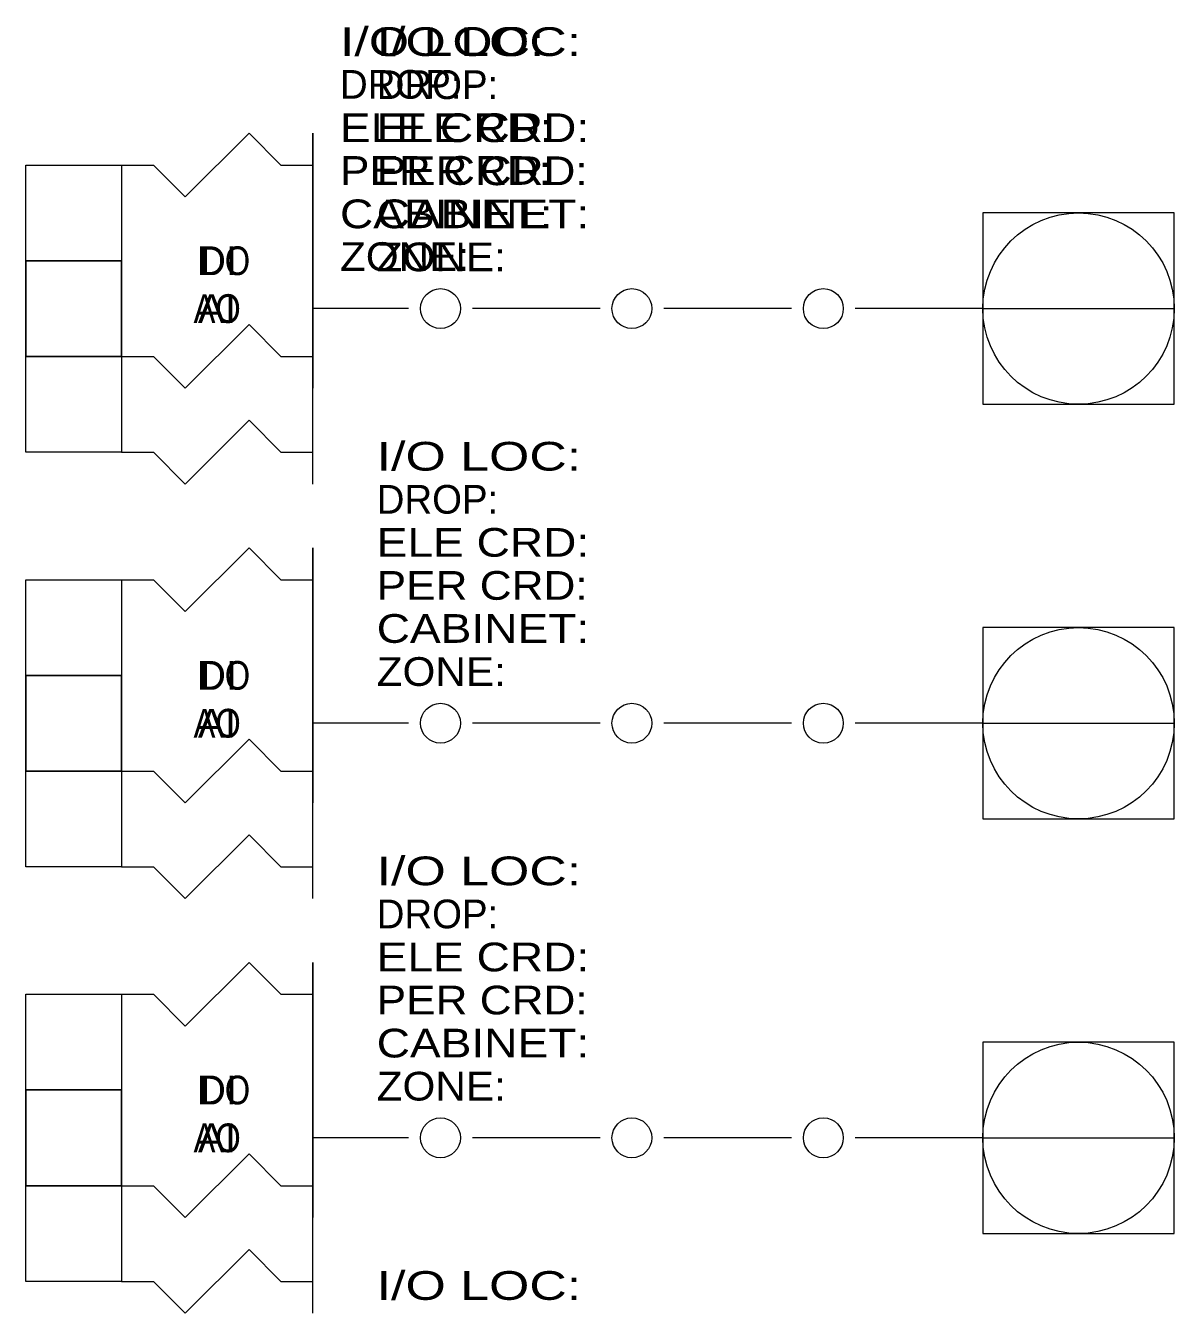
# Model space of a CAD drawing. Extents: x 0.01 to 1.26, y 0 to 0.83.
# Drawn here: x 0.9583 to 1.2583, y 0.4958 to 0.8322 of the extents above; entities that cross this region are included whole.
import ezdxf
from ezdxf.enums import TextEntityAlignment as Align

# ---------------------------------------------------------------- set-up
doc = ezdxf.new("R2010")
doc.units = 0
doc.header["$LTSCALE"] = 0.003
for name, color, linetype, lineweight in [('1', 7, 'Continuous', 13), ('10', 7, 'Continuous', 13), ('11', 7, 'Continuous', 13), ('12', 7, 'Continuous', 13), ('13', 7, 'Continuous', 13), ('14', 7, 'Continuous', 13), ('19', 7, 'Continuous', 13), ('2', 7, 'Continuous', 13), ('20', 7, 'Continuous', 13), ('21', 7, 'Continuous', 13), ('22', 7, 'Continuous', 13), ('23', 7, 'Continuous', 13), ('24', 7, 'Continuous', 13), ('29', 7, 'Continuous', 13), ('3', 7, 'Continuous', 13), ('30', 7, 'Continuous', 13), ('39', 7, 'Continuous', 13), ('4', 7, 'Continuous', 13), ('40', 7, 'Continuous', 13), ('9', 7, 'Continuous', 13)]:
    doc.layers.add(name, color=color, linetype=linetype, lineweight=lineweight)

msp = doc.modelspace()

# ---------------------------------------------------------------- linework, layer by layer
at = {"layer": '1'}
for p, q in [((1.033333, 0.804166), (1.033333, 0.7375)), ((0.958333, 0.770833), (0.958333, 0.745833)), ((0.983333, 0.745833), (0.983333, 0.770833)), ((0.958333, 0.745833), (0.983333, 0.745833))]:
    msp.add_line(p, q, dxfattribs=at)
for points in [[(0.983333, 0.795833), (0.991666, 0.795833), (1, 0.7875), (1.016666, 0.804166), (1.025, 0.795833), (1.033333, 0.795833)], [(0.983333, 0.745833), (0.991666, 0.745833), (1, 0.7375), (1.016666, 0.754166), (1.025, 0.745833), (1.033333, 0.745833)]]:
    msp.add_lwpolyline(points, dxfattribs=at)
msp.add_lwpolyline([(0.958333, 0.795833), (0.983333, 0.795833), (0.983333, 0.770833), (0.958333, 0.770833)], close=True, dxfattribs=at)
at = {"layer": '10'}
for p, q in [((1.058333, 0.758333), (1.033333, 0.758333)), ((1.108333, 0.758333), (1.075, 0.758333)), ((1.158333, 0.758333), (1.125, 0.758333)), ((1.208333, 0.758333), (1.175, 0.758333)), ((1.208333, 0.758333), (1.258333, 0.758333))]:
    msp.add_line(p, q, dxfattribs=at)
msp.add_lwpolyline([(1.208333, 0.783333), (1.208333, 0.733333), (1.258333, 0.733333), (1.258333, 0.783333)], close=True, dxfattribs=at)
for centre, radius in [((1.233333, 0.758333), 0.025), ((1.066666, 0.758333), 0.005208), ((1.116666, 0.758333), 0.005208), ((1.166666, 0.758333), 0.005208)]:
    msp.add_circle(centre, radius, dxfattribs=at)
at = {"layer": '11'}
msp.add_line((1.033333, 0.695833), (1.033333, 0.629166), dxfattribs=at)
for points in [[(0.983333, 0.6875), (0.991666, 0.6875), (1, 0.679166), (1.016666, 0.695833), (1.025, 0.6875), (1.033333, 0.6875)], [(0.958333, 0.6625), (0.958333, 0.6375), (0.983333, 0.6375), (0.983333, 0.6625)], [(0.983333, 0.6375), (0.991666, 0.6375), (1, 0.629166), (1.016666, 0.645833), (1.025, 0.6375), (1.033333, 0.6375)]]:
    msp.add_lwpolyline(points, dxfattribs=at)
msp.add_lwpolyline([(0.958333, 0.6875), (0.983333, 0.6875), (0.983333, 0.6625), (0.958333, 0.6625)], close=True, dxfattribs=at)
at = {"layer": '12'}
for p, q in [((1.033333, 0.695833), (1.033333, 0.629166)), ((0.958333, 0.6625), (0.983333, 0.6625))]:
    msp.add_line(p, q, dxfattribs=at)
for points in [[(0.983333, 0.6875), (0.991666, 0.6875), (1, 0.679166), (1.016666, 0.695833), (1.025, 0.6875), (1.033333, 0.6875)], [(0.983333, 0.6375), (0.991666, 0.6375), (1, 0.629166), (1.016666, 0.645833), (1.025, 0.6375), (1.033333, 0.6375)]]:
    msp.add_lwpolyline(points, dxfattribs=at)
msp.add_lwpolyline([(0.958333, 0.6875), (0.983333, 0.6875), (0.983333, 0.6375), (0.958333, 0.6375)], close=True, dxfattribs=at)
at = {"layer": '13'}
for p, q in [((1.033333, 0.604166), (1.033333, 0.695833)), ((0.958333, 0.6625), (0.983333, 0.6625)), ((0.958333, 0.6375), (0.983333, 0.6375))]:
    msp.add_line(p, q, dxfattribs=at)
for points in [[(0.983333, 0.6875), (0.991666, 0.6875), (1, 0.679166), (1.016666, 0.695833), (1.025, 0.6875), (1.033333, 0.6875)], [(0.983333, 0.6125), (0.991666, 0.6125), (1, 0.604166), (1.016666, 0.620833), (1.025, 0.6125), (1.033333, 0.6125)]]:
    msp.add_lwpolyline(points, dxfattribs=at)
msp.add_lwpolyline([(0.958333, 0.6875), (0.983333, 0.6875), (0.983333, 0.6125), (0.958333, 0.6125)], close=True, dxfattribs=at)
at = {"layer": '14'}
for p, q in [((1.033333, 0.604166), (1.033333, 0.695833)), ((0.958333, 0.6625), (0.983333, 0.6625)), ((0.958333, 0.6375), (0.983333, 0.6375))]:
    msp.add_line(p, q, dxfattribs=at)
for points in [[(0.983333, 0.6875), (0.991666, 0.6875), (1, 0.679166), (1.016666, 0.695833), (1.025, 0.6875), (1.033333, 0.6875)], [(0.983333, 0.6125), (0.991666, 0.6125), (1, 0.604166), (1.016666, 0.620833), (1.025, 0.6125), (1.033333, 0.6125)]]:
    msp.add_lwpolyline(points, dxfattribs=at)
msp.add_lwpolyline([(0.958333, 0.6875), (0.983333, 0.6875), (0.983333, 0.6125), (0.958333, 0.6125)], close=True, dxfattribs=at)
at = {"layer": '19'}
for p, q in [((1.058333, 0.65), (1.033333, 0.65)), ((1.108333, 0.65), (1.075, 0.65)), ((1.158333, 0.65), (1.125, 0.65)), ((1.208333, 0.65), (1.175, 0.65)), ((1.208333, 0.65), (1.258333, 0.65))]:
    msp.add_line(p, q, dxfattribs=at)
msp.add_lwpolyline([(1.208333, 0.675), (1.208333, 0.625), (1.258333, 0.625), (1.258333, 0.675)], close=True, dxfattribs=at)
for centre, radius in [((1.233333, 0.65), 0.025), ((1.066666, 0.65), 0.005208), ((1.116666, 0.65), 0.005208), ((1.166666, 0.65), 0.005208)]:
    msp.add_circle(centre, radius, dxfattribs=at)
at = {"layer": '2'}
for p, q in [((1.033333, 0.804166), (1.033333, 0.7375)), ((0.958333, 0.770833), (0.983333, 0.770833))]:
    msp.add_line(p, q, dxfattribs=at)
for points in [[(0.983333, 0.795833), (0.991666, 0.795833), (1, 0.7875), (1.016666, 0.804166), (1.025, 0.795833), (1.033333, 0.795833)], [(0.983333, 0.745833), (0.991666, 0.745833), (1, 0.7375), (1.016666, 0.754166), (1.025, 0.745833), (1.033333, 0.745833)]]:
    msp.add_lwpolyline(points, dxfattribs=at)
msp.add_lwpolyline([(0.958333, 0.795833), (0.983333, 0.795833), (0.983333, 0.745833), (0.958333, 0.745833)], close=True, dxfattribs=at)
at = {"layer": '20'}
for p, q in [((1.058333, 0.65), (1.033333, 0.65)), ((1.108333, 0.65), (1.075, 0.65)), ((1.158333, 0.65), (1.125, 0.65)), ((1.208333, 0.65), (1.175, 0.65)), ((1.208333, 0.65), (1.258333, 0.65))]:
    msp.add_line(p, q, dxfattribs=at)
msp.add_lwpolyline([(1.208333, 0.675), (1.208333, 0.625), (1.258333, 0.625), (1.258333, 0.675)], close=True, dxfattribs=at)
for centre, radius in [((1.233333, 0.65), 0.025), ((1.066666, 0.65), 0.005208), ((1.116666, 0.65), 0.005208), ((1.166666, 0.65), 0.005208)]:
    msp.add_circle(centre, radius, dxfattribs=at)
at = {"layer": '21'}
msp.add_line((1.033333, 0.5875), (1.033333, 0.520833), dxfattribs=at)
for points in [[(0.983333, 0.579166), (0.991666, 0.579166), (1, 0.570833), (1.016666, 0.5875), (1.025, 0.579166), (1.033333, 0.579166)], [(0.958333, 0.554166), (0.958333, 0.529166), (0.983333, 0.529166), (0.983333, 0.554166)], [(0.983333, 0.529166), (0.991666, 0.529166), (1, 0.520833), (1.016666, 0.5375), (1.025, 0.529166), (1.033333, 0.529166)]]:
    msp.add_lwpolyline(points, dxfattribs=at)
msp.add_lwpolyline([(0.958333, 0.579166), (0.983333, 0.579166), (0.983333, 0.554166), (0.958333, 0.554166)], close=True, dxfattribs=at)
at = {"layer": '22'}
for p, q in [((1.033333, 0.5875), (1.033333, 0.520833)), ((0.958333, 0.554166), (0.983333, 0.554166))]:
    msp.add_line(p, q, dxfattribs=at)
for points in [[(0.983333, 0.579166), (0.991666, 0.579166), (1, 0.570833), (1.016666, 0.5875), (1.025, 0.579166), (1.033333, 0.579166)], [(0.983333, 0.529166), (0.991666, 0.529166), (1, 0.520833), (1.016666, 0.5375), (1.025, 0.529166), (1.033333, 0.529166)]]:
    msp.add_lwpolyline(points, dxfattribs=at)
msp.add_lwpolyline([(0.958333, 0.579166), (0.983333, 0.579166), (0.983333, 0.529166), (0.958333, 0.529166)], close=True, dxfattribs=at)
at = {"layer": '23'}
for p, q in [((1.033333, 0.495833), (1.033333, 0.5875)), ((0.958333, 0.554166), (0.983333, 0.554166)), ((0.958333, 0.529166), (0.983333, 0.529166))]:
    msp.add_line(p, q, dxfattribs=at)
for points in [[(0.983333, 0.579166), (0.991666, 0.579166), (1, 0.570833), (1.016666, 0.5875), (1.025, 0.579166), (1.033333, 0.579166)], [(0.983333, 0.504166), (0.991666, 0.504166), (1, 0.495833), (1.016666, 0.5125), (1.025, 0.504166), (1.033333, 0.504166)]]:
    msp.add_lwpolyline(points, dxfattribs=at)
msp.add_lwpolyline([(0.958333, 0.579166), (0.983333, 0.579166), (0.983333, 0.504166), (0.958333, 0.504166)], close=True, dxfattribs=at)
at = {"layer": '24'}
for p, q in [((1.033333, 0.495833), (1.033333, 0.5875)), ((0.958333, 0.554166), (0.983333, 0.554166)), ((0.958333, 0.529166), (0.983333, 0.529166))]:
    msp.add_line(p, q, dxfattribs=at)
for points in [[(0.983333, 0.579166), (0.991666, 0.579166), (1, 0.570833), (1.016666, 0.5875), (1.025, 0.579166), (1.033333, 0.579166)], [(0.983333, 0.504166), (0.991666, 0.504166), (1, 0.495833), (1.016666, 0.5125), (1.025, 0.504166), (1.033333, 0.504166)]]:
    msp.add_lwpolyline(points, dxfattribs=at)
msp.add_lwpolyline([(0.958333, 0.579166), (0.983333, 0.579166), (0.983333, 0.504166), (0.958333, 0.504166)], close=True, dxfattribs=at)
at = {"layer": '29'}
for p, q in [((1.058333, 0.541666), (1.033333, 0.541666)), ((1.108333, 0.541666), (1.075, 0.541666)), ((1.158333, 0.541666), (1.125, 0.541666)), ((1.208333, 0.541666), (1.175, 0.541666)), ((1.208333, 0.541666), (1.258333, 0.541666))]:
    msp.add_line(p, q, dxfattribs=at)
msp.add_lwpolyline([(1.208333, 0.566666), (1.208333, 0.516666), (1.258333, 0.516666), (1.258333, 0.566666)], close=True, dxfattribs=at)
for centre, radius in [((1.233333, 0.541666), 0.025), ((1.066666, 0.541666), 0.005208), ((1.116666, 0.541666), 0.005208), ((1.166666, 0.541666), 0.005208)]:
    msp.add_circle(centre, radius, dxfattribs=at)
at = {"layer": '3'}
for p, q in [((1.033333, 0.7125), (1.033333, 0.804166)), ((0.958333, 0.770833), (0.983333, 0.770833)), ((0.958333, 0.745833), (0.983333, 0.745833))]:
    msp.add_line(p, q, dxfattribs=at)
for points in [[(0.983333, 0.795833), (0.991666, 0.795833), (1, 0.7875), (1.016666, 0.804166), (1.025, 0.795833), (1.033333, 0.795833)], [(0.983333, 0.720833), (0.991666, 0.720833), (1, 0.7125), (1.016666, 0.729166), (1.025, 0.720833), (1.033333, 0.720833)]]:
    msp.add_lwpolyline(points, dxfattribs=at)
msp.add_lwpolyline([(0.958333, 0.795833), (0.983333, 0.795833), (0.983333, 0.720833), (0.958333, 0.720833)], close=True, dxfattribs=at)
at = {"layer": '30'}
for p, q in [((1.058333, 0.541666), (1.033333, 0.541666)), ((1.108333, 0.541666), (1.075, 0.541666)), ((1.158333, 0.541666), (1.125, 0.541666)), ((1.208333, 0.541666), (1.175, 0.541666)), ((1.208333, 0.541666), (1.258333, 0.541666))]:
    msp.add_line(p, q, dxfattribs=at)
msp.add_lwpolyline([(1.208333, 0.566666), (1.208333, 0.516666), (1.258333, 0.516666), (1.258333, 0.566666)], close=True, dxfattribs=at)
for centre, radius in [((1.233333, 0.541666), 0.025), ((1.066666, 0.541666), 0.005208), ((1.116666, 0.541666), 0.005208), ((1.166666, 0.541666), 0.005208)]:
    msp.add_circle(centre, radius, dxfattribs=at)
at = {"layer": '4'}
for p, q in [((1.033333, 0.7125), (1.033333, 0.804166)), ((0.958333, 0.770833), (0.983333, 0.770833)), ((0.958333, 0.745833), (0.983333, 0.745833))]:
    msp.add_line(p, q, dxfattribs=at)
for points in [[(0.983333, 0.795833), (0.991666, 0.795833), (1, 0.7875), (1.016666, 0.804166), (1.025, 0.795833), (1.033333, 0.795833)], [(0.983333, 0.720833), (0.991666, 0.720833), (1, 0.7125), (1.016666, 0.729166), (1.025, 0.720833), (1.033333, 0.720833)]]:
    msp.add_lwpolyline(points, dxfattribs=at)
msp.add_lwpolyline([(0.958333, 0.795833), (0.983333, 0.795833), (0.983333, 0.720833), (0.958333, 0.720833)], close=True, dxfattribs=at)
at = {"layer": '9'}
for p, q in [((1.058333, 0.758333), (1.033333, 0.758333)), ((1.108333, 0.758333), (1.075, 0.758333)), ((1.158333, 0.758333), (1.125, 0.758333)), ((1.208333, 0.758333), (1.175, 0.758333)), ((1.208333, 0.758333), (1.258333, 0.758333))]:
    msp.add_line(p, q, dxfattribs=at)
msp.add_lwpolyline([(1.208333, 0.783333), (1.208333, 0.733333), (1.258333, 0.733333), (1.258333, 0.783333)], close=True, dxfattribs=at)
for centre, radius in [((1.233333, 0.758333), 0.025), ((1.066666, 0.758333), 0.005208), ((1.116666, 0.758333), 0.005208), ((1.166666, 0.758333), 0.005208)]:
    msp.add_circle(centre, radius, dxfattribs=at)

# ---------------------------------------------------------------- texts
at = {"layer": '1', "width": 1.05}
msp.add_text('DI', height=0.0075, dxfattribs=at).set_placement((1.008291, 0.767083), align=Align.CENTER)
at = {"layer": '10'}
for s, width, p in [('I/O LOC:', 1.35, (1.040416, 0.824333)), ('ELE CRD:', 1.2, (1.040416, 0.801833)), ('PER CRD:', 1.15, (1.040416, 0.790666)), ('CABINET:', 1.2, (1.040416, 0.779333)), ('ZONE:', 1.1, (1.040416, 0.768166))]:
    msp.add_text(s, height=0.0075, dxfattribs=dict(at, width=width)).set_placement(p)
msp.add_text('DROP:', height=0.0075, dxfattribs=at).set_placement((1.040416, 0.813166))
at = {"layer": '11', "width": 1.05}
msp.add_text('DI', height=0.0075, dxfattribs=at).set_placement((1.008291, 0.65875), align=Align.CENTER)
at = {"layer": '12', "width": 0.85}
msp.add_text('DO', height=0.0075, dxfattribs=at).set_placement((1.004166, 0.65875))
at = {"layer": '13', "width": 1.05}
msp.add_text('AI', height=0.0075, dxfattribs=at).set_placement((1.008291, 0.64625), align=Align.CENTER)
at = {"layer": '14', "width": 0.85}
msp.add_text('AO', height=0.0075, dxfattribs=at).set_placement((1.008333, 0.64625), align=Align.CENTER)
at = {"layer": '19'}
for s, width, p in [('I/O LOC:', 1.35, (1.05, 0.716)), ('ELE CRD:', 1.2, (1.05, 0.6935)), ('PER CRD:', 1.15, (1.05, 0.68225)), ('CABINET:', 1.2, (1.05, 0.671)), ('ZONE:', 1.1, (1.05, 0.65975))]:
    msp.add_text(s, height=0.0075, dxfattribs=dict(at, width=width)).set_placement(p)
msp.add_text('DROP:', height=0.0075, dxfattribs=at).set_placement((1.05, 0.70475))
at = {"layer": '2', "width": 0.85}
msp.add_text('DO', height=0.0075, dxfattribs=at).set_placement((1.004166, 0.767083))
at = {"layer": '20'}
for s, width, p in [('I/O LOC:', 1.35, (1.05, 0.716)), ('ELE CRD:', 1.2, (1.05, 0.6935)), ('PER CRD:', 1.15, (1.05, 0.68225)), ('CABINET:', 1.2, (1.05, 0.671)), ('ZONE:', 1.1, (1.05, 0.65975))]:
    msp.add_text(s, height=0.0075, dxfattribs=dict(at, width=width)).set_placement(p)
msp.add_text('DROP:', height=0.0075, dxfattribs=at).set_placement((1.05, 0.70475))
at = {"layer": '21', "width": 1.05}
msp.add_text('DI', height=0.0075, dxfattribs=at).set_placement((1.008291, 0.550416), align=Align.CENTER)
at = {"layer": '22', "width": 0.85}
msp.add_text('DO', height=0.0075, dxfattribs=at).set_placement((1.004166, 0.550416))
at = {"layer": '23', "width": 1.05}
msp.add_text('AI', height=0.0075, dxfattribs=at).set_placement((1.008291, 0.537916), align=Align.CENTER)
at = {"layer": '24', "width": 0.85}
msp.add_text('AO', height=0.0075, dxfattribs=at).set_placement((1.008333, 0.537916), align=Align.CENTER)
at = {"layer": '29'}
for s, width, p in [('I/O LOC:', 1.35, (1.05, 0.607666)), ('ELE CRD:', 1.2, (1.05, 0.585166)), ('PER CRD:', 1.15, (1.05, 0.573916)), ('CABINET:', 1.2, (1.05, 0.562666)), ('ZONE:', 1.1, (1.05, 0.551416))]:
    msp.add_text(s, height=0.0075, dxfattribs=dict(at, width=width)).set_placement(p)
msp.add_text('DROP:', height=0.0075, dxfattribs=at).set_placement((1.05, 0.596416))
at = {"layer": '3', "width": 1.05}
msp.add_text('AI', height=0.0075, dxfattribs=at).set_placement((1.008291, 0.754583), align=Align.CENTER)
at = {"layer": '30'}
for s, width, p in [('I/O LOC:', 1.35, (1.05, 0.607666)), ('ELE CRD:', 1.2, (1.05, 0.585166)), ('PER CRD:', 1.15, (1.05, 0.573916)), ('CABINET:', 1.2, (1.05, 0.562666)), ('ZONE:', 1.1, (1.05, 0.551416))]:
    msp.add_text(s, height=0.0075, dxfattribs=dict(at, width=width)).set_placement(p)
msp.add_text('DROP:', height=0.0075, dxfattribs=at).set_placement((1.05, 0.596416))
at = {"layer": '39', "width": 1.35}
msp.add_text('I/O LOC:', height=0.0075, dxfattribs=at).set_placement((1.05, 0.499333))
at = {"layer": '4', "width": 0.85}
msp.add_text('AO', height=0.0075, dxfattribs=at).set_placement((1.008333, 0.754583), align=Align.CENTER)
at = {"layer": '40', "width": 1.35}
msp.add_text('I/O LOC:', height=0.0075, dxfattribs=at).set_placement((1.05, 0.499333))
at = {"layer": '9'}
for s, width, p in [('I/O LOC:', 1.35, (1.05, 0.824333)), ('ELE CRD:', 1.2, (1.05, 0.801833)), ('PER CRD:', 1.15, (1.05, 0.790583)), ('CABINET:', 1.2, (1.05, 0.779333)), ('ZONE:', 1.1, (1.05, 0.768083))]:
    msp.add_text(s, height=0.0075, dxfattribs=dict(at, width=width)).set_placement(p)
msp.add_text('DROP:', height=0.0075, dxfattribs=at).set_placement((1.05, 0.813083))

doc.saveas('drawing.dxf')
